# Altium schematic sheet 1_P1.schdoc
size 309 x 223 mm; Symbol: Sheet-Symbol_A4; Device: Sheet-Symbol_A4; @Page Name: P1; @Create Date: 2023-08-15; @Page Count: 1; @Page No: 1; @Project Name: BPF-42_42-front-endpanel; @Schematic Name: Schematic1; @Update Date: 2023-08-15; Company: 嘉立创EDA; Page Size: A4; Version: V1.0
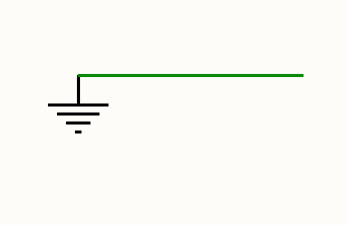
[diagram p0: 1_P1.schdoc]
